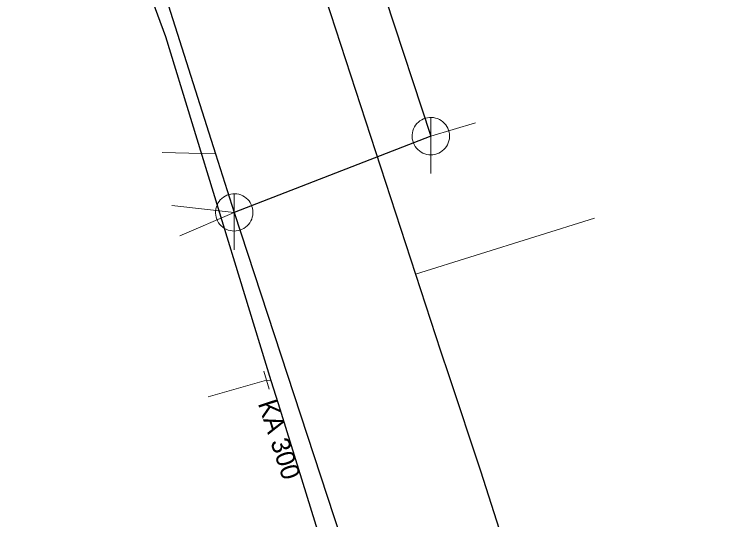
# Model space of a CAD drawing. Extents: x -807203 to -805207, y -993656 to -992505.
# Drawn here: x -807110.31 to -807072.84, y -993157.85 to -993130.79 of the extents above; entities that cross this region are included whole.
import ezdxf

# ---------------------------------------------------------------- set-up
doc = ezdxf.new("R2010")
doc.units = 0
doc.header["$LTSCALE"] = 0.4
for name, color, linetype, lineweight in [('1', 7, 'Continuous', 13), ('11', 7, 'Continuous', 13), ('13', 7, 'Continuous', 13), ('14', 7, 'Continuous', 25), ('17', 7, 'Continuous', 25), ('22', 7, 'Continuous', 13), ('34', 7, 'Continuous', 13)]:
    doc.layers.add(name, color=color, linetype=linetype, lineweight=lineweight)

msp = doc.modelspace()

# ---------------------------------------------------------------- linework, layer by layer
at = {"layer": '11'}
for p, q in [((-807085.642, -993136.607), (-807088.03, -993137.32)), ((-807102.392, -993138.196), (-807099.532, -993138.273)), ((-807101.877, -993141.028), (-807098.539, -993141.399)), ((-807101.447, -993142.658), (-807098.539, -993141.399))]:
    msp.add_line(p, q, dxfattribs=at)
at = {"layer": '13'}
for p, q in [((-807088.843, -993144.709), (-807079.283, -993141.713)), ((-807096.815, -993150.378), (-807099.937, -993151.269))]:
    msp.add_line(p, q, dxfattribs=at)
at = {"layer": '14'}
for p, q in [((-807097.09, -993109.699), (-807088.03, -993137.32)), ((-807088.03, -993137.32), (-807098.539, -993141.399)), ((-807098.539, -993141.399), (-807090.379, -993166.289))]:
    msp.add_line(p, q, dxfattribs=at)
at = {"layer": '14', "lineweight": 13}
msp.add_line((-807096.815, -993150.378), (-807096.589, -993150.385), dxfattribs=at)
at = {"layer": '14'}
msp.add_lwpolyline([(-807110.309, -993104.32), (-807109.321, -993107.433), (-807106.151, -993117.421), (-807099.532, -993138.273), (-807098.539, -993141.399)], dxfattribs=at)
at = {"layer": '17'}
for points in [[(-807102.744, -993101.5), (-807102.241, -993103.247), (-807100.675, -993108.116), (-807100.243, -993109.059), (-807099.234, -993112.603), (-807098.39, -993115.482), (-807094.98, -993125.833), (-807093.653, -993129.923), (-807088.842, -993144.708), (-807087.517, -993148.8), (-807087.074, -993150.114), (-807085.368, -993155.225), (-807083.942, -993159.686), (-807072.827, -993193.081), (-807070.855, -993198.727), (-807058.136, -993236.557), (-807055.798, -993243.556), (-807050.671, -993258.89), (-807046.204, -993272.388), (-807040.605, -993289.576), (-807026.284, -993334.262)], [(-807106.216, -993120.722), (-807103.627, -993128.16), (-807102.219, -993132), (-807096.589, -993150.385), (-807096.195, -993151.629), (-807092.921, -993162.153), (-807079.791, -993202.059), (-807064.89, -993246.39), (-807059.596, -993262.052), (-807055.035, -993275.397), (-807053.806, -993278.989)]]:
    msp.add_lwpolyline(points, dxfattribs=at)
at = {"layer": '22'}
for p, q in [((-807088.03, -993139.32), (-807088.029, -993136.32)), ((-807098.539, -993143.399), (-807098.538, -993140.399))]:
    msp.add_line(p, q, dxfattribs=at)
for points in [[(-807087.03, -993137.32), (-807087.035, -993137.211), (-807087.053, -993137.103), (-807087.083, -993136.997), (-807087.123, -993136.896), (-807087.175, -993136.799), (-807087.237, -993136.709), (-807087.309, -993136.626), (-807087.389, -993136.552), (-807087.477, -993136.486), (-807087.571, -993136.431), (-807087.671, -993136.386), (-807087.776, -993136.353), (-807087.883, -993136.331), (-807087.992, -993136.321), (-807088.102, -993136.323), (-807088.21, -993136.337), (-807088.317, -993136.362), (-807088.42, -993136.399), (-807088.518, -993136.448), (-807088.61, -993136.506), (-807088.696, -993136.575), (-807088.773, -993136.652), (-807088.842, -993136.738), (-807088.901, -993136.83), (-807088.949, -993136.928), (-807088.986, -993137.031), (-807089.012, -993137.138), (-807089.026, -993137.246), (-807089.029, -993137.356), (-807089.019, -993137.465), (-807088.998, -993137.572), (-807088.964, -993137.676), (-807088.92, -993137.776), (-807088.865, -993137.871), (-807088.799, -993137.959), (-807088.725, -993138.039), (-807088.642, -993138.111), (-807088.552, -993138.173), (-807088.456, -993138.225), (-807088.354, -993138.266), (-807088.249, -993138.296), (-807088.141, -993138.314), (-807088.031, -993138.32), (-807087.922, -993138.314), (-807087.814, -993138.296), (-807087.709, -993138.267), (-807087.607, -993138.226), (-807087.51, -993138.174), (-807087.42, -993138.112), (-807087.337, -993138.041), (-807087.262, -993137.961), (-807087.197, -993137.873), (-807087.141, -993137.779), (-807087.097, -993137.679), (-807087.063, -993137.575), (-807087.041, -993137.467), (-807087.031, -993137.358)], [(-807097.539, -993141.399), (-807097.544, -993141.29), (-807097.562, -993141.182), (-807097.592, -993141.076), (-807097.632, -993140.975), (-807097.684, -993140.878), (-807097.746, -993140.788), (-807097.818, -993140.705), (-807097.898, -993140.631), (-807097.986, -993140.565), (-807098.08, -993140.51), (-807098.18, -993140.465), (-807098.285, -993140.432), (-807098.392, -993140.41), (-807098.501, -993140.4), (-807098.611, -993140.402), (-807098.719, -993140.416), (-807098.826, -993140.441), (-807098.929, -993140.478), (-807099.027, -993140.527), (-807099.119, -993140.585), (-807099.205, -993140.654), (-807099.282, -993140.731), (-807099.351, -993140.817), (-807099.41, -993140.909), (-807099.458, -993141.007), (-807099.495, -993141.11), (-807099.521, -993141.217), (-807099.535, -993141.325), (-807099.538, -993141.435), (-807099.528, -993141.544), (-807099.507, -993141.651), (-807099.473, -993141.755), (-807099.429, -993141.855), (-807099.374, -993141.95), (-807099.308, -993142.038), (-807099.234, -993142.118), (-807099.151, -993142.19), (-807099.061, -993142.252), (-807098.965, -993142.304), (-807098.863, -993142.345), (-807098.758, -993142.375), (-807098.65, -993142.393), (-807098.54, -993142.399), (-807098.431, -993142.393), (-807098.323, -993142.375), (-807098.218, -993142.346), (-807098.116, -993142.305), (-807098.019, -993142.253), (-807097.929, -993142.191), (-807097.846, -993142.12), (-807097.771, -993142.04), (-807097.706, -993141.952), (-807097.65, -993141.858), (-807097.606, -993141.758), (-807097.572, -993141.654), (-807097.55, -993141.546), (-807097.54, -993141.437)]]:
    msp.add_lwpolyline(points, close=True, dxfattribs=at)
at = {"layer": '34'}
msp.add_line((-807096.677, -993150.858), (-807096.951, -993149.897), dxfattribs=at)

# ---------------------------------------------------------------- texts
at = {"layer": '1'}
msp.add_text('KA 300', height=1, rotation=288, dxfattribs=at).set_placement((-807097.28, -993151.612))

doc.saveas('drawing.dxf')
